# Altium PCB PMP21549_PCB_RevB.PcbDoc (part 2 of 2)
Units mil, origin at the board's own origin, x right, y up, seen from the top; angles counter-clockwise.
Board outline 4798 x 2992 mil, 2 copper layers (Top Layer, Bottom Layer), stack 62 mil thick; 82 components, 39 nets, 178 pads, 21 vias.
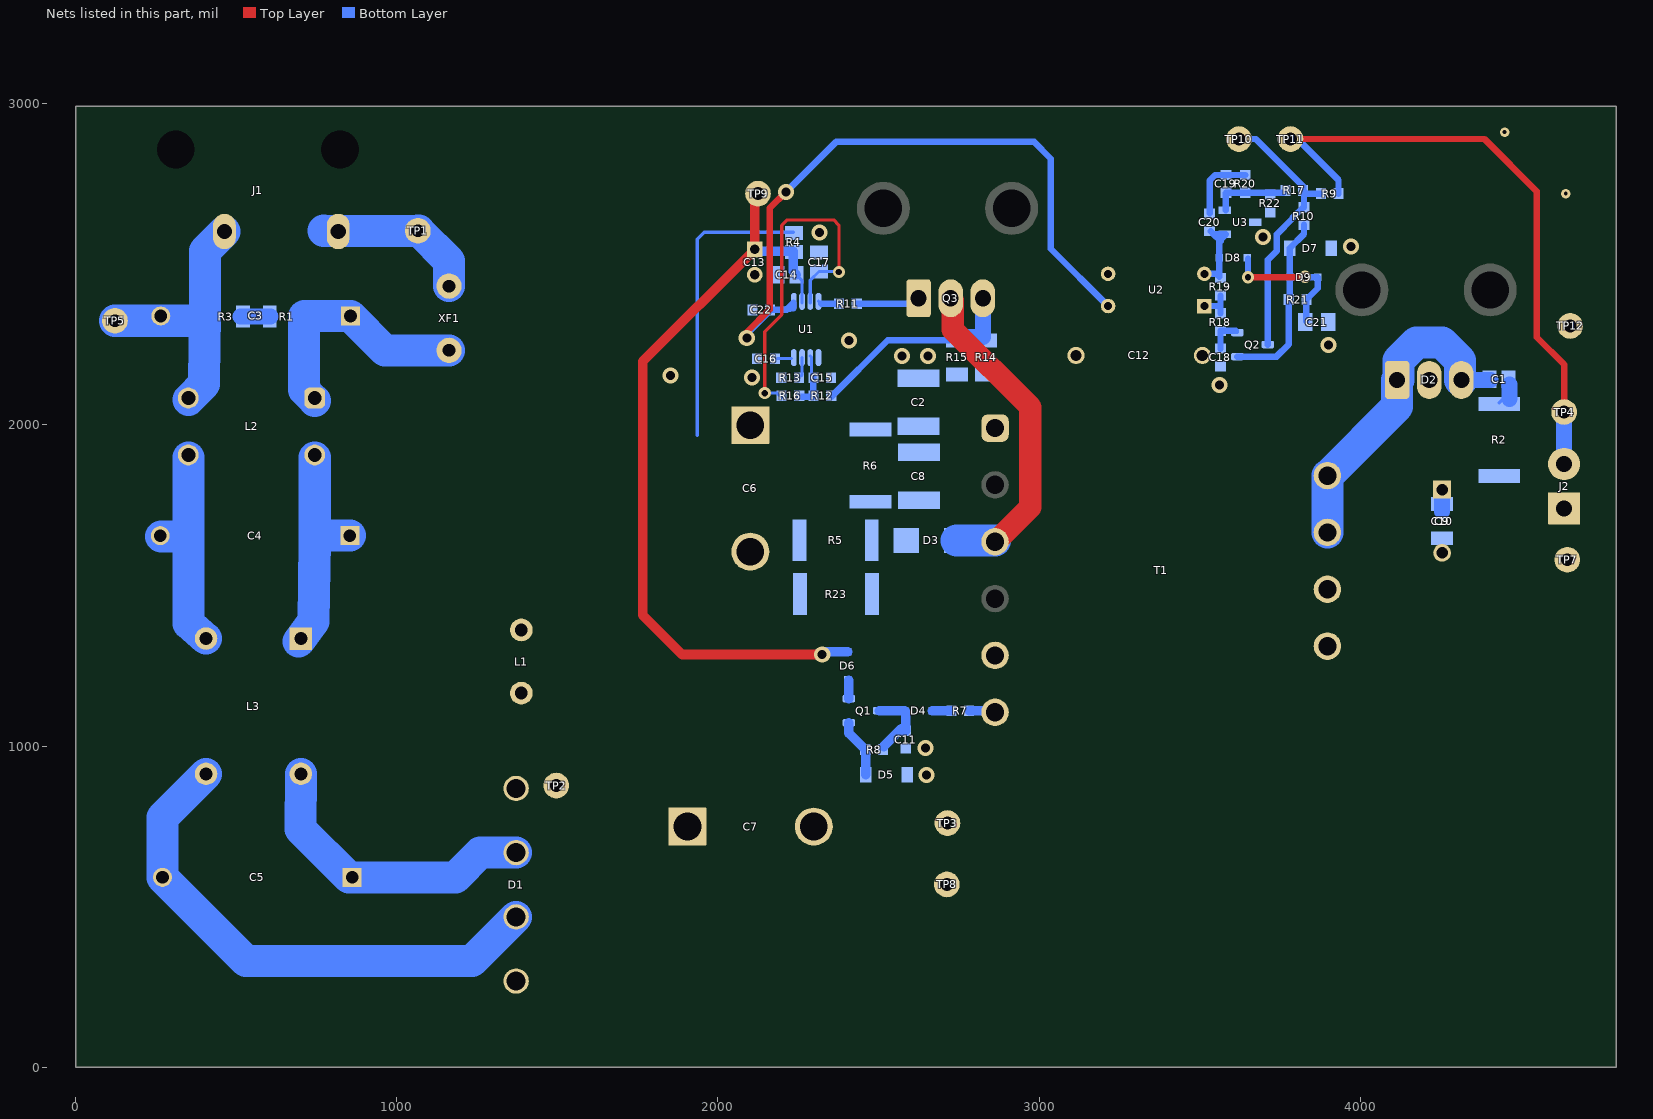
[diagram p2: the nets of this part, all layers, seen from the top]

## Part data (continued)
R18 R19: library part CMP-0022109-4, "RES, 1.00 k, 1%, 0.1 W, 0603", Manufacturer=Vishay-Dale, Power_W=100mW, Supplier Part Number 1=541-1.00KHCT-ND, TempCo="100 ppm/C", Tolerance_%=1%, Value2=0.1W, Value_Code=1k00, ValueDisplayed=1.00k
R20: library part CMP-0022684-3, "RES, 10.0 k, 1%, 0.1 W, 0603", Manufacturer=Panasonic, Power_W=100mW, Supplier Part Number 1=P10.0KHCT-ND, TempCo="100 ppm/C", Tolerance_%=1%, Value2=0.1W, Value_Code=10k0, ValueDisplayed=10.0k
R21: library part CMP-0021990-3, "RES, 100 k, 1%, 0.1 W, 0603", Manufacturer=Vishay-Dale, Power_W=100mW, Supplier Part Number 1=541-100KHCT-ND, TempCo="100 ppm/C", Tolerance_%=1%, Value2=0.1W, Value_Code=100k
R22: library part CMP-0022277-3, "RES, 2.49 k, 1%, 0.1 W, 0603", Manufacturer=Vishay-Dale, Power_W=100mW, Supplier Part Number 1=541-2.49KHCT-ND, TempCo="100 ppm/C", Tolerance_%=1%, Value2=0.1W, Value_Code=2k49, ValueDisplayed=2.49k
T1: library part CMP-0078825-2, "Transformer, 1050 uH, TH", Manufacturer="Renco Electronics", ValueDisplayed=1.05mH
TP1 TP2 TP4 TP5 TP9 TP10 TP11: library part CMP-0055137-1, "Test Point, Miniature, Red, TH", Color=Red, Manufacturer=Keystone, Supplier Part Number 1=36-5000-ND
TP3 TP7 TP8 TP12: library part CMP-0055138-1, "Test Point, Miniature, Black, TH", Color=Black, Manufacturer=Keystone, Supplier Part Number 1=36-5001-ND
U1: library part CMP-0072830-2, "AC-DC Current Mode PWM Controller, DGK0008A (VSSOP-8)", Manufacturer="Texas Instruments"
U2: library part CMP-0006173-3, "Optocoupler, 5 kV, 80-160% CTR, TH", Manufacturer="Fairchild Semiconductor", Supplier Part Number 1=FOD817A-ND, Voltage_Isolation_Vrms=5kV
U3: library part CMP-0033091-1, "Adjustable Precision Shunt Regulator, 34 ppm / degC, 100 mA, -40 to 85 degC, 3-pin SOT-23 (DBZ), Green (RoHS & no Sb/Br)", Manufacturer="Texas Instruments", Rating=Catalog, Temp Coeff(Max)(ppm/ degree C)=92, Temp Coeff(Typ)(ppm/ degree C)=34
XF1: library part CMP-0003627-1, "Fuse Holder, TR5, TH", Manufacturer=Littelfuse, Supplier Part Number 1=WK6235-ND

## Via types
v1: diameter 50, hole 28, Top Layer to Bottom Layer, 15 vias
v2: diameter 38, hole 20, Top Layer to Bottom Layer, 4 vias
v3: diameter 29.92, hole 12.2, Top Layer to Bottom Layer, 2 vias

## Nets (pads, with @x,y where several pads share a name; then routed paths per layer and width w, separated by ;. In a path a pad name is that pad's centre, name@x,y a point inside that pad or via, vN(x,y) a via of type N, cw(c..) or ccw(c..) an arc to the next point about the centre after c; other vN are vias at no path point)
NetC1_1: C1.1 R2.2 | length 84.9
  Bottom Layer w10: R2.2@4432.82,2069.14 4462,2098.32
  Bottom Layer w50: R2.2@4465,2081.32 C1.1@4465,2125
NetC1_2: C1.2 D2.1 D2.3 T1.9 T1.10 | length 1021.9
  Bottom Layer w50: D2.3@4315,2140 C1.2@4406.16,2140
  Bottom Layer w100: T1.9@3898,1665 T1.10@3898,1842 ; T1.10@3901,1843 4115,2057 D2.1@4115,2140 4119.13,2140 4119.13,2200.77 4175.29,2256.93 4254.71,2256.93 4310.87,2200.77 4310.87,2140 D2.3@4315,2140
NetC2_1: C2.1 C6.1 C8.1 L1.2 R4.2 R5.2 R6.2 R23.2 T1.1 | length 918.9
  Bottom Layer w10: 1936,1967 1936,2578 1957.53,2599.53 R4.2@2235,2599.53
NetC3_1: C3.1 L2.1 R1.2 XF1.1 | length 773.1
  Bottom Layer w10: R1.2@711,2337 R1.2@713,2339
  Bottom Layer w100: R1.2@711,2337 711,2109.17 L2.1@745,2075.17 ; R1.2@713,2339 C3.1@856,2339 963,2232 XF1.1@1163,2232
NetC3_2: C3.2 J1.2 L2.4 R3.1 TP5.1 | length 843.4
  Bottom Layer w10: L2.4@351.3,2075.17 L2.4@351.3,2078
  Bottom Layer w100: TP5.1@122.76,2324.25 R3.1@394,2324.25 ; L2.4@351.3,2078 400,2126.7 400,2144.8 403.27,2337.19 403.27,2541.68 J1.2@463.67,2602.08
NetC4_1: C4.1 L2.2 L3.1 | length 710.3
  Bottom Layer w100: L3.1@694,1325 741,1388 745,1633 745,1685 ; L2.2@745,1898 745,1685 ; C4.1@854.28,1655 775,1655 745,1685
NetC4_2: C4.2 L2.3 L3.2 | length 673.2
  Bottom Layer w100: C4.2@266.72,1652 351.3,1652 ; L2.3@351.3,1898 351.3,1652 ; L3.2@406.36,1334.63 351.3,1382 351.3,1652
NetC5_1: C5.1 D1.2 L3.4 | length 937.4
  Bottom Layer w100: L3.4@701.64,913.37 700.97,741.03 851,591 C5.1@861.28,591 1183,591 1260,668 D1.2@1372,668
NetC5_2: C5.2 D1.3 L3.3 | length 1644.3
  Bottom Layer w100: L3.3@406.36,913.37 270.72,777.73 C5.2@270.72,591 530.72,331 1235,331 D1.3@1372,468
NetC7_1: C7.1 D1.1 L1.1 TP2.1
NetC8_2: C8.2 D3.1 R5.1 R6.1 R23.1
NetC9_1: C9.1 C10.1 D2.2 J2.2 R2.1 R9.2 TP4.1 TP11.1 | length 2039.4
  Top Layer w20: TP11.1@3783,2890 4386.87,2890 4550,2726.87 4550,2272.64 4635,2187.64 TP4.1@4635,2040
  Bottom Layer w20: TP11.1@3783,2890 TP11.1@3805,2890 ; TP11.1@3812,2890 TP11.1@3805,2890 ; R9.2@3932.56,2720 3932.56,2762.44 TP11.1@3805,2890
  Bottom Layer w50: 4255,1729.52 C10.1@4255,1753.15 C9.1@4255,1798.42 ; J2.2@4635,1878 TP4.1@4635,2040
NetC11_1: C11.1 D4.1 Q1.3 R8.2 | length 239.9
  Bottom Layer w10: C11.1@2570.12,1045.02 C11.1@2570.12,1047.56
  Bottom Layer w30: Q1.3@2502.24,1110 D4.1@2581.69,1110 2585,1106.69 C11.1@2585,1047.56 C11.1@2570.12,1047.56 ; R8.2@2516,998 C11.1@2572.02,1054.02
NetC13_1: C13.1 C14.1 D6.1 R4.1 TP9.1 U1.2 | length 2440.2
  Top Layer w30: TP9.1@2125,2720 2115,2710 C13.1@2115,2546.38 1766,2197.38 1766,1408 1889,1285 v1(2325,1285)
  Bottom Layer w10: C14.1@2244.53,2467.01 2262.2,2449.33 U1.2@2262.2,2379.68
  Bottom Layer w30: C13.1@2120.91,2540.47 2235,2540.47 2235,2476.54 C14.1@2244.53,2467.01 ; v1(2325,1285) 2333.31,1293.31 D6.1@2405,1293.31
NetC15_1: C15.1 R12.1 R16.2 U1.6 | length 176.2
  Bottom Layer w10: U1.6@2287.8,2214.33 2291.65,2210.47 2291.65,2152.8 C15.1@2297.44,2147.01
  Bottom Layer w20: R16.2@2252.56,2087.01 2297.44,2087.01 C15.1@2297.44,2147.01
NetC16_1: C16.1 U1.8 | length 46.7
  Bottom Layer w10: C16.1@2182.56,2207.01 U1.8@2229.29,2207.01
NetC17_1: C17.1 R16.1 U1.3 | length 1107.6
  Top Layer w10: v2(2146,2099) 2146,2290.44 2198.87,2343.31 2198.87,2620.87 2216,2638 2361,2638 2377,2622 v2(2377,2476)
  Bottom Layer w10: v2(2146,2099) 2185.45,2099 R16.1@2197.44,2087.01 ; U1.3@2287.8,2379.68 2287.8,2450.28 C17.1@2315,2477.48 v2@2375.52,2477.48
NetC18_1: C18.1 Q2.2 R18.2 | length 109.7
  Bottom Layer w10: Q2.2@3612.72,2292.44 Q2.2@3617.76,2287.4
  Bottom Layer w20: C18.1@3565,2237.56 R18.2@3565,2292.44 Q2.2@3612.72,2292.44
NetC19_1: C19.1 R17.1 R20.2 R22.2 U3.2 | length 243.7
  Bottom Layer w10: C19.1@3581.25,2721.8 C19.1@3582.2,2722.76 ; R17.1@3760.2,2722.76 R17.1@3767.44,2730
  Bottom Layer w20: U3.2@3581.25,2667.72 C19.1@3581.25,2721.8 ; C19.1@3582.2,2722.76 R20.2@3642.2,2722.76 R17.1@3760.2,2722.76
NetC19_2: C19.2 C20.1 R20.1 | length 220
  Bottom Layer w20: C20.1@3531,2658.56 3531,2760 3548.87,2777.87 C19.2@3582.2,2777.87 R20.1@3642.2,2777.87
NetC20_2: C20.2 D8.2 R19.1 U2.2 U3.1 | length 272.2
  Bottom Layer w20: U2.2@3515,2470 3552.56,2470 3561.69,2460.87 D8.2@3561.69,2520 3561.69,2572.91 3581.69,2592.91 C20.2@3544.84,2592.91 ; C20.2@3535,2602.76 C20.2@3544.84,2592.91 ; 3566.5,2571.26 3563.27,2574.49 C20.2@3544.84,2592.91
NetC21_1: C21.1 D8.1 D9.2 R21.1 | length 425.5
  Top Layer w20: v2(3650.62,2459.88) v2@3827.62,2459.88
  Bottom Layer w20: v2(3650.62,2459.88) D8.1@3650.62,2517.69 ; v2@3829.5,2460 D9.2@3868.31,2460 3868.31,2425.75 R21.1@3832.56,2390 C21.1@3832.56,2322.91
  other v2: 3828.62,2460.88
NetC22_1: C22.1 U1.1 U2.4 | length 2184.3
  Top Layer w20: v1(2090,2270) 2090,2288 2161,2359 2161,2674 v1(2212,2725)
  Bottom Layer w20: v1(2090,2270) 2090,2282.8 2162.56,2355.36 C22.1@2162.56,2358 ; C22.1@2161,2359 2214.79,2359 2216.23,2360.45 ; 2212.01,2360 2216.23,2360.45 ; v1@2217,2730 2368,2881 2985,2881 3037,2829 3037,2548 U2.4@3215,2370 ; 2216.23,2360.45 2235.47,2379.68 2235.47,2362.47 2216.23,2360.45
NetD3_2: D3.2 Q3.2 T1.3 | length 1023.5
  Top Layer w70: Q3.2@2725,2394.2 2732,2387.2 2732,2296 2973,2055 2973,1744 T1.3@2866,1637
  Bottom Layer w100: D3.2@2743.74,1640 T1.3@2863,1640
NetD4_2: D4.2 R7.2 | length 59.1
  Bottom Layer w30: D4.2@2668.31,1110 R7.2@2727.44,1110
NetD5_1: D5.1 Q1.1 R8.1 | length 180.1
  Bottom Layer w30: Q1.1@2407.76,1072.6 2407.76,1039.69 R8.1@2457.44,990 ; D5.1@2460.53,910 R8.1@2460.53,986.91
NetD6_2: D6.2 Q1.2 | length 56.5
  Bottom Layer w30: Q1.2@2407.76,1147.4 D6.2@2407.76,1203.94
NetD7_1: D7.1 D9.1 Q2.1 R10.1 R21.2 | length 567.1
  Bottom Layer w20: Q2.1@3617.76,2212.6 3739.6,2212.6 3777.44,2250.44 R21.2@3777.44,2390 3780.53,2393.09 D7.1@3780.53,2550 3825,2594.47 R10.1@3825,2622.44
NetJ1_1: J1.1 TP1.1 XF1.2 | length 507.3
  Bottom Layer w10: 1002.68,2604.33 1002.76,2604.25
  Bottom Layer w100: 772.76,2604.33 818.02,2603.97 TP1.1@1066,2604.25 1068.56,2604.25 1163,2509.82 XF1.2@1163,2432
NetQ2_3: Q2.3 R9.1 R10.2 R17.2 TP10.1 | length 854.9
  Bottom Layer w20: TP10.1@3622.6,2890 3675,2890 3822.56,2742.44 R17.2@3822.56,2730 ; Q2.3@3712.24,2250 3712.24,2513.5 3740.87,2542.13 3740.87,2593.43 3790.39,2642.95 3790.39,2645.59 3822.36,2677.56 R10.2@3825,2677.56 3825,2727.56 3832.56,2720 R9.1@3877.44,2720
NetQ3_1: Q3.1 R11.2 | length 199.6
  Bottom Layer w20: R11.2@2432.56,2377.01 2607.8,2377.01 Q3.1@2625,2394.2
NetQ3_3: Q3.3 R12.2 R14.2 R15.2 | length 656.5
  Bottom Layer w20: R12.2@2352.56,2087.01 2528.7,2263.15 R15.2@2745,2263.15
  Bottom Layer w50: R15.2@2755,2273.15 2825,2273.15 Q3.3@2825,2394.2
NetR1_1: R1.1 R3.2 | length 93.7
  Bottom Layer w50: R3.2@513.57,2337 R1.1@607.28,2337
NetR7_1: R7.1 T1.6 | length 82.5
  Bottom Layer w10: T1.6@2858,1110 T1.6@2863,1105
  Bottom Layer w30: R7.1@2782.56,1110 T1.6@2858,1110
NetR11_1: R11.1 U1.4 | length 67.3
  Bottom Layer w10: U1.4@2313.39,2384.61 U1.4@2321.29,2376.7
  Bottom Layer w20: U1.4@2321.29,2376.7 R11.1@2377.44,2376.7
NetR13_2: R13.2 U1.7 | length 66.4
  Bottom Layer w10: R13.2@2252.56,2147.01 2262.2,2156.65 U1.7@2262.2,2209.41
NetR18_1: R18.1 R19.2 U2.1 | length 104.9
  Bottom Layer w20: U2.1@3515,2370 3565,2370 ; R18.1@3565,2347.56 3565,2370 ; R19.2@3565,2402.44 3565,2370
"pwr gnd": C2.2 C6.2 C7.2 C11.2 C12.2 C13.2 C14.2 C15.2 C16.2 C17.2 C22.2 D1.4 D5.2 R13.1 R14.1 R15.1 T1.5 TP3.1 TP8.1 U1.5 U2.3
  other v1: 2649,910 2646,994 2106,2148 1853,2153 2574,2215 2655,2215 2408,2263 2317,2599
"SEC GND": C9.2 C10.2 C12.1 C18.2 C21.2 D7.2 J2.1 R22.1 T1.7 T1.8 TP7.1 TP12.1 U3.3
  other v1: 3562,2124 3901,2249 3971,2555 3698,2585
  other v3: 4640,2720 4450,2911.4
pads on no net: H1.MH1 H1.MH2 H2.MH1 H2.MH2 J1.MH1 J1.MH2 T1.2 T1.4

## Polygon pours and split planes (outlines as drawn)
NetC8_2 on Bottom Layer "BOTTOM_LAYER_NETC8_2_P003" (solid, remove dead copper, pour order 3): 2709,1826 2709,1392 2401.19,1392 2401.19,1826
"SEC GND" on Bottom Layer "BOTTOM_LAYER_SEC_GND_P022" (solid, remove dead copper, pour order 22): 3471,2940 3471,2071 3832,2071 3832,50 4747.53,50 4752.57,2940
NetC9_1 on Bottom Layer "BOTTOM_LAYER_NETC9_1_P020" (solid, remove dead copper, pour order 20): 4167,2205 4278,2205 4287,2196 4287,1967 4301,1953 4709,1953 4709,1811 4701,1803 4314,1803 4281,1770 4192,1770 4173,1789
"pwr gnd" on Bottom Layer "BOTTOM_LAYER_PWR_GND_P016" (solid, remove dead copper, pour order 16): 1285.23,50 2955,50 2955,2080 3019,2144 3241.76,2144 3241.76,2940 1482,2940 1482,436 1382,336 1287,336
NetC2_1 on Bottom Layer "BOTTOM_LAYER_NETC2_1_P001" (solid, remove dead copper, pour order 1): 1294,1313 2403.3,1313 2403.3,1840 2932.63,1840 2932.63,2060 1294,2060
NetC9_1 on Top Layer "TOP_LAYER_NETC9_1_P000" (solid, remove dead copper, pour order 0): 4284.3,1743.3 4343,1802 4701,1802 4701,1947 4695,1953 4170.63,1953 4170.63,1791.37 4218.7,1743.3
"SEC GND" on Top Layer "TOP_LAYER_SEC_GND_P018" (solid, remove dead copper, pour order 18): 3469,2940 3469,2085 3832,2085 3832,50 4750,50 4750,2940
"pwr gnd" on Top Layer "TOP_LAYER_PWR_GND_P005" (solid, remove dead copper, pour order 5): 1287,50 2955,50 2955,2051 3019,2144 3241.76,2144 3241.76,2940 1482,2940 1477,429 1287,245.11
NetC7_1 on Top Layer "TOP_LAYER_NETC7_1_P004" (solid, remove dead copper, pour order 4): 1979,674 1538,674 1401,811 1291,811 1291,1202 1298,1209 1301,1206 1586,1206 1979,822.05

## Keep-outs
Keep-Out Layer:
  text ".Layer_Name" at 577,-858.49 h60

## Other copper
Top Layer:
  text ".Layer_Name" at 577,-858.49 h60
Bottom Layer:
  text ".Layer_Name" at 577,-858.49 h60

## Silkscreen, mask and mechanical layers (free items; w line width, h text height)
Top Overlay:
  region: 1000,213 700,213 700,113 1000,113
  text "'.PRJ_Number'.PCB_Rev-" at 117,130.77 h108.27
  text ".Layer_Name" at 577,-858.49 h60
Bottom Overlay:
  lines w10: 3643,2810 3667,2834 3669,2834
  text ".Layer_Name" at 577,-858.49 h60
Top Paste:
  text ".Layer_Name" at 577,-858.49 h60
Bottom Paste:
  text ".Layer_Name" at 577,-858.49 h60
Top Solder:
  text ".Layer_Name" at 577,-858.49 h60
  text ".Layer_Name" at 577,-858.49 h60
Bottom Solder:
  text ".Layer_Name" at 577,-858.49 h60
Drill Guide:
  text ".Layer_Name" at 577,-858.49 h60
M1 Board Outline:
  lines w10: 0,2992 0,0 4798,0 4799,2992 1,2992
  text ".Layer_Name" at 577,-858.49 h60
M2 Board Dimensions:
  rectangle: 125,-400 500,-275
  rectangle: 0,-275 125,-150
  lines w7: 0,-275 1000,-275 ; 125,-400 125,-150 ; 250,-400 250,-150 ; 500,-400 500,-150 ; 750,-400 750,-150 ; 0,-400 0,-150 1000,-150 1000,-400 0,-400
  text ".Layer_Name" at 577,-858.49 h60
M3 3D STEP Top:
  text ".Layer_Name" at 577,-858.49 h60
M4 3D STEP Bottom:
  text ".Layer_Name" at 577,-858.49 h60
M5 Assembly Top:
  lines w10: -292,-930.17 6308,-930.17 ; -292,-726.83 6310,-726.83 ; -292,-523.5 -292,-1133.5 3713,-1133.5 6310,-1133.5 6310,-523.5 -291.5,-523.5 -291.5,-1133.5 1284,-1133.5 ; 2173,-1133.5 2173,-523.5 ; 3440,-726.83 3440,-523.5 ; 4280,-726.83 4280,-523.5 ; 4902,-1140 4902,-937.17
  text "COMPONENTS MARKED 'DNP' SHOULD NOT BE POPULATED." at 1153.5,-318.5 h60
  text "ASSEMBLY VARIANT:" at 1153,-434 h60
  text ".VariantName" at 2189,-434 h60
  text "PCB VIEWED FROM TOP SIDE" at -228.5,-655.67 h60
  text "BOARD #:" at 2248,-655.67 h60
  text ".PRJ_Number" at 2793.5,-655.67 h60
  text "REV:" at 3638,-655.67 h60
  text ".PCB_Rev" at 3929.5,-655.67 h60
  text "SVN REV:" at 4476,-655.67 h60
  text ".VersionControl_RevNumber" at 4982,-655.67 h60
  text "TID #:" at 2248,-859 h60
  text ".TID" at 2793.5,-859 h60
  text "PLOT NAME =" at -228.5,-1064.34 h60
  text ".plot_File_Name" at 577,-1064.34 h60
  text "GENERATED    :" at 2250,-1064.34 h60
  text ".Print_Date" at 3119.5,-1064.34 h60
  text ".Print_Time" at 3848.5,-1064.34 h60
  text "TEXAS INSTRUMENTS" at 5113,-1064.34 h60
M6 Assembly Bottom:
  lines w10: -292.5,-727.33 6309.5,-727.33 ; -290.5,-930.67 6309.5,-930.67 ; 1115.5,-1140.5 1115.5,-937.67 ; 1737.5,-727.33 1737.5,-524 ; 2577.5,-727.33 2577.5,-524 ; 3844.5,-1134 3844.5,-524 ; 4733.5,-1134 6309,-1134 6309,-524 -292.5,-524 -292.5,-1134 2304.5,-1134 6309.5,-1134 6309.5,-524
  text "COMPONENTS MARKED 'DNP' SHOULD NOT BE POPULATED." at 6102,-318 h60
  text ".VariantName" at 5058,-434 h60
  text "ASSEMBLY VARIANT:" at 6097,-434 h60
  text ".VersionControl_RevNumber" at 1035.5,-656.17 h60
  text "SVN REV:" at 1541.5,-656.17 h60
  text ".PCB_Rev" at 2088,-656.17 h60
  text "REV:" at 2379.5,-656.17 h60
  text ".PRJ_Number" at 3224,-656.17 h60
  text "BOARD #:" at 3769.5,-656.17 h60
  text "PCB VIEWED FROM BOTTOM SIDE" at 6246,-656.17 h60
  text ".TID" at 3224,-859.5 h60
  text "TID #:" at 3769.5,-859.5 h60
  text "TEXAS INSTRUMENTS" at 904.5,-1064.84 h60
  text ".Print_Time" at 2169,-1064.84 h60
  text ".Print_Date" at 2898,-1064.84 h60
  text "GENERATED    :" at 3767.5,-1064.84 h60
  text ".plot_File_Name" at 5440.5,-1064.84 h60
  text "PLOT NAME =" at 6246,-1064.84 h60
M9 Title Sheet:
  drawing of 57 lines, arcs and shapes, not listed
  text "1" at 739.84,8036.5 h70
  text "2" at 3235.5,8036.5 h70
  text "3" at 5724.84,8036.5 h70
  text "4" at 8231.51,8036.5 h70
  text "5" at 10730.5,8036.5 h70
  text "6" at 13235.5,8036.5 h70
  text "A" at -416.5,6893.5 h70
  text "A" at 14383.5,6893.5 h70
  text "B" at -416.5,4513.5 h70
  text "B" at 14383.5,4513.5 h70
  text "C" at -416.5,2138.5 h70
  text "C" at 14383.5,2138.5 h70
  text "PROJECT TITLE:" at 11343.5,277.5 h45
  text ".PRJ_Title" at 11393.5,144.17 h70
  text "DESIGNED FOR:" at 11343.5,-23.5 h45
  text ".PRJ_Customer" at 11393.5,-163.5 h70
  text "D" at -416.5,-231.5 h70
  text "D" at 14383.5,-231.5 h70
  text "FILE NAME:" at 11343.5,-323.5 h45
  text ".PCB_File_Name_No_Path" at 11393.5,-443.5 h70
  text "Texas Instruments (TI) and/or its licensors do not warrant the accuracy or completeness of this specification" at 6374,-605.34 h45
  text "ENGINEER:" at 11343.5,-613.5 h45
  text "LAYOUT BY:" at 12848.5,-613.5 h45
  text "or any information contained therein. TI and/or its licensors do not warrant that this design will meet" at 6329.01,-718 h45
  text ".PRJ_Engineer" at 11393.5,-768.49 h70
  text ".PCB_Layout" at 12899,-768.49 h70
  text "the specifications, will be suitable for your application or fit for any particular purpose, or will operate in" at 6329.01,-830.67 h45
  text ".Layer_Name" at 577,-858.49 h60
  text "ALTIUM DESIGNER VERSION:" at 12848.5,-923.5 h45
  text "an implementation. TI and/or its licensors do not warrant that the design is production worthy. You should" at 6329.01,-943.33 h45
  text "completely validate and test your design implementation to confirm the system functionality for your application." at 6374,-1056 h45
  text ".print_Scale" at 11393.5,-1056.83 h70
  text ".Application_BuildNumber" at 12899,-1056.83 h70
  text "1" at 739.84,-1263.5 h70
  text "2" at 3235.5,-1263.5 h70
  text "3" at 5724.84,-1263.5 h70
  text "4" at 8231.51,-1263.5 h70
  text "5" at 10730.5,-1263.5 h70
  text "6" at 13235.5,-1263.5 h70
M10 Fab Notes:
  drawing of 189 lines, arcs and shapes, not listed
  text "DESIGN INFORMATION" at 12382.02,6356.17 h60
  text "MIN. TRACK WIDTH:" at 11737.46,6224.05 h60
  text "8" at 12833.7,6224.05 h60
  text "MIL" at 12988.46,6224.05 h60
  text "MIN. CLEARANCE:" at 11737.46,6099.92 h60
  text "0.2" at 12773.7,6099.93 h60
  text "mm" at 12988.46,6099.92 h60
  text "MIN. VIA PAD SIZE:" at 11737.46,5975.8 h60
  text "24" at 12803.71,5975.8 h60
  text "MIL" at 12988.46,5975.8 h60
  text "0.05mm (2MIL)" at 12432.46,5845.9 h60
  text "MINIMUM ANNULAR RING" at 11408.23,5837.67 h60
  text "EXTERNAL" at 13140.46,5837.67 h60
  text "PER" at 11608.23,5727.55 h60
  text "IPC-D-275 CLASS 2 LEVEL C" at 11828.23,5727.54 h60
  text "MIL, HOLES" at 13316.46,5627.07 h60
  text "+/-" at 12924,5618.48 h60
  text "+/-" at 13778,5618.48 h60
  text "REGISTRATION TOLERANCES:" at 11408.23,5617.42 h60
  text "METAL" at 12608,5617.42 h60
  text "5" at 13184.2,5617.42 h60
  text "3" at 14017.2,5617.42 h60
  text "MIL" at 14133.46,5617.42 h60
  text "HOLE SIZE TOLERANCE (UNLESS OTHERWISE SPECIFIED):" at 11408.23,5519.1 h60
  text "+/-" at 13778,5516.23 h60
  text "3" at 14017.2,5515.17 h60
  text "MIL" at 14133.46,5515.17 h60
  text "MATERIAL:" at 11333.46,5377.52 h60
  text "FR-4 High Tg" at 12319.9,5249 h60
  text "X" at 12175.46,5241.01 h60
  text "FR-408" at 11754.46,5236.49 h60
  text "OTHER" at 13242.46,5236.49 h60
  text "62 MIL (1.6mm) +/-10%" at 12074.56,5093.46 h60
  text "X" at 11954.46,5091.01 h60
  text "THICKNESS:" at 11408.23,5085.24 h60
  text "OTHER" at 13359.46,5085.24 h60
  text "TOLERANCE:" at 11408.23,4946.92 h60
  text "X" at 12256.46,4946.92 h60
  text "ANSI IPC-6012 TYPE 3 CLASS 2" at 12434.48,4946.92 h60
  text "OTHER +/-" at 12434.46,4802.73 h60
  text "BOW & TWIST:" at 11408.23,4657.54 h60
  text "X" at 12256.46,4657.54 h60
  text "ANSI IPC-6012 TYPE 3 CLASS 2" at 12434.48,4657.54 h60
  text "OTHER +/-" at 12434.46,4510.85 h60
  text "DRILLING:" at 11333.46,4380.23 h60
  text "NC_DRILL FILES" at 13094.46,4275.04 h60
  text "REFERENCE:" at 11408.23,4271.1 h60
  text "X" at 12065.46,4271.01 h60
  text "AS SHOWN" at 12243.46,4271.1 h60
  text "X" at 12966.46,4271.1 h60
  text "OTHER" at 13392.46,4128.85 h60
  text "PTH COPPER THICKNESS:" at 11407.91,4125.32 h60
  text "X" at 12547.14,4125.32 h60
  text "20-30 um" at 12675.14,4125.32 h60
  text "BOARD FINISH:" at 11333.46,3977.73 h60
  text "SILKSCREEN:" at 11488.68,3867.6 h60
  text "X" at 12446.46,3867.6 h60
  text "TOP" at 12563.46,3867.6 h60
  text "X" at 12956.46,3867.6 h60
  text "BOTTOM" at 13074.46,3867.6 h60
  text "SILKSCREEN COLOR:" at 11488.68,3712.41 h60
  text "X" at 12445.46,3712.41 h60
  text "WHITE" at 12563.46,3712.41 h60
  text "OTHER" at 13074.46,3712.41 h60
  text "X" at 12576.46,3568.96 h60
  text "GREEN" at 12694.46,3568.96 h60
  text "OTHER" at 13312.46,3568.96 h60
  text "SOLDER RESIST COLOR:" at 11488.68,3562.1 h60
  text "X" at 12576.46,3414.71 h60
  text "MATTE" at 12694.46,3414.71 h60
  text "SEMI-GLOSS" at 13312,3414.07 h60
  text "IMMERSION GOLD (ENIG)" at 12394.46,3241.94 h60
  text "ENEPIG" at 13732,3234.72 h60
  text "SURFACE FINISH:" at 11333.46,3233.72 h60
  text "X" at 12216.46,3233.72 h60
  text "IMM. TIN/SILVER OR EQUIV" at 11663,3096.4 h60
  text "OTHER" at 13094.46,3092.47 h60
  text "ARRAY/PANEL:" at 11333.46,2937.09 h60
  text "CUT AND TRIM PER M1 BOARD OUTLINE" at 12394.46,2928.87 h60
  text "N.C. ROUTE" at 12394.46,2792.9 h60
  text "X" at 13082.46,2792.9 h60
  text "V. SCORE" at 13260.46,2792.9 h60
  text "CERTIFICATION:" at 11333.46,2663.77 h60
  text "MATERIALS AND WORKMANSHIP FOR ALL PCBS" at 12058.46,2663.77 h60
  text "TO MEET OR EXCEED THE REQUIREMENTS OF:" at 12058.46,2569.71 h60
  text "X" at 11695.97,2441.08 h60
  text "ANSI IPC-A-600F CLASS ->" at 11823.96,2441.08 h60
  text "X" at 13471.97,2441.08 h60
  text "2" at 13581.96,2441.08 h60
  text "1" at 13266.96,2439.58 h60
  text "3" at 13935.96,2439.58 h60
  text "X" at 12507.97,2293.39 h60
  text "RoHS" at 12635.96,2293.39 h60
  text "OTHER" at 13280.36,2293.39 h60
  text "PER ORDER" at 13677.42,2293.39 h60
  text "ALL BOARDS MUST MEET OR EXCEED UL94-V0 REQUIREMENTS." at 11361,2139.57 h60
  text "PCB MUST BEAR THE UL94V-0 UL REGISTERED MATERIAL ID NUMBER" at 11361,2023.5 h60
  text "ADDITIONAL REQUIREMENTS:" at 11333.46,1854.08 h60
  text "MICROSECTION:" at 11408.23,1746.95 h60
  text "YES" at 12313.96,1746.95 h60
  text "REQUIRED" at 13175.46,1602.62 h60
  text "BARE BOARD ELEC. TEST:" at 11408.23,1599.76 h60
  text "NONE" at 12713.96,1599.76 h60
  text "X" at 13057.46,1599.76 h60
  text "PER ORDER" at 13767.46,1599.76 h60
  text "XX MIL VIAS REQUIRE NON-CONDUCTIVE FILL AND PLANARIZE" at 11576.38,1394.82 h59
  text "XX MIL VIAS REQUIRE CONDUCTIVE FILL AND PLANARIZE" at 11584.38,1290.84 h60
  text "OUTER XX MIL TRACES REQUIRE 50 OHM SINGLE-ENDED IMPEDANCE" at 11583.39,1127.46 h58
  text "LAYER 2 & 3 (INNER LAYERS) XX MIL WIDE, XX MIL SPACE / TRACES REQUIRE 100 OHM DIFFERENTIAL IMPEDANCE" at 11575.39,891.74 h60
  text ".Layer_Name" at 577,-858.49 h60
M11 Gerber Information:
  lines w10: -292,-930.17 6308,-930.17 ; -292,-726.83 6310,-726.83 ; -292,-523.5 -292,-1133.5 3713,-1133.5 6310,-1133.5 6310,-523.5 -291.5,-523.5 -291.5,-1133.5 1284,-1133.5 ; 2173,-1133.5 2173,-523.5 ; 3440,-726.83 3440,-523.5 ; 4280,-726.83 4280,-523.5 ; 4902,-1140 4902,-937.17
  text "ALL ARTWORK VIEWED FROM TOP SIDE" at -228.5,-655.67 h60
  text "BOARD #:" at 2248,-655.67 h60
  text ".PRJ_Number" at 2793.5,-655.67 h60
  text "REV:" at 3638,-655.67 h60
  text ".PCB_Rev" at 3929.5,-655.67 h60
  text "SVN REV:" at 4476,-655.67 h60
  text ".VersionControl_RevNumber" at 4982,-655.67 h60
  text "LAYER NAME =" at -228.5,-858.49 h60
  text "TID #:" at 2248,-859 h60
  text ".TID" at 2793.5,-859 h60
  text "PLOT NAME =" at -228.5,-1064.34 h60
  text ".plot_File_Name" at 577,-1064.34 h60
  text "GENERATED    :" at 2250,-1064.34 h60
  text ".Print_Date" at 3119.5,-1064.34 h60
  text ".Print_Time" at 3848.5,-1064.34 h60
  text "TEXAS INSTRUMENTS" at 5113,-1064.34 h60
M12 Stackup:
  drawing of 191 lines, arcs and shapes, not listed
  text "Layer" at 9797.84,7582.5 h60
  text "Name" at 10207.76,7582.5 h60
  text "Material" at 11137.5,7582.5 h60
  text "Thickness" at 11997.27,7582.5 h60
  text "Constant" at 12647.1,7582.5 h60
  text "Board Layer Stack" at 13216.96,7582.5 h60
  text "1" at 9797.84,7462.5 h60
  text "Top Overlay" at 10207.76,7462.5 h60
  text "2" at 9797.84,7342.5 h60
  text "Top Solder" at 10207.76,7342.5 h60
  text "Solder Resist" at 11137.5,7342.5 h60
  text "0.40mil" at 11997.27,7342.5 h60
  text "3.5" at 12647.1,7342.5 h60
  text "3" at 9797.84,7222.5 h60
  text "Top Layer" at 10207.76,7222.5 h60
  text "Copper" at 11137.5,7222.5 h60
  text "1.40mil" at 11997.27,7222.5 h60
  text "4" at 9797.84,7102.5 h60
  text "Dielectric1" at 10207.76,7102.5 h60
  text "FR-4" at 11137.5,7102.5 h60
  text "59.20mil" at 11997.27,7102.5 h60
  text "4.8" at 12647.1,7102.5 h60
  text "5" at 9797.84,6982.5 h60
  text "Bottom Layer" at 10207.76,6982.5 h60
  text "Copper" at 11137.5,6982.5 h60
  text "1.40mil" at 11997.27,6982.5 h60
  text "6" at 9797.84,6862.5 h60
  text "Bottom Solder" at 10207.76,6862.5 h60
  text "Solder Resist" at 11137.5,6862.5 h60
  text "0.40mil" at 11997.27,6862.5 h60
  text "3.5" at 12647.1,6862.5 h60
  text "7" at 9797.84,6742.5 h60
  text "Bottom Overlay" at 10207.76,6742.5 h60
  text ".Layer_Name" at 577,-858.49 h60
M13 Component Bodies Top:
  text ".Layer_Name" at 577,-858.49 h60
M14 Component Bodies Bottom:
  text ".Layer_Name" at 577,-858.49 h60
M15 Courtyards Top:
  text ".Layer_Name" at 577,-858.49 h60
M16 Courtyards Bottom:
  text ".Layer_Name" at 577,-858.49 h60
Drill Drawing:
  circle w10: c5363.72,3407.23 r27.63
  lines w10: 5336.09,1639.12 5363.72,1652.93 5391.34,1639.12 5377.53,1666.75 5391.34,1694.37 5363.72,1680.56 5336.09,1694.37 5349.9,1666.75 5336.09,1639.12 ; 5336.09,1777.25 5349.9,1777.25 5349.9,1763.44 5377.53,1763.44 5377.53,1777.25 5391.34,1777.25 5391.34,1804.88 5377.53,1804.88 5377.53,1818.69 5349.9,1818.69 5349.9,1804.88 5336.09,1804.88 5336.09,1777.25 ; 5336.09,1887.76 5336.09,1901.57 5349.9,1915.39 5336.09,1929.2 5336.09,1943.01 5349.9,1943.01 5363.72,1929.2 5377.53,1943.01 5391.34,1943.01 5391.34,1929.2 5377.53,1915.39 5391.34,1901.57 5391.34,1887.76 5377.53,1887.76 5363.72,1901.57 5349.9,1887.76 5336.09,1887.76 ; 5336.09,2012.08 5363.72,2025.89 5391.34,2012.08 5377.53,2039.71 5391.34,2067.33 5363.72,2053.52 5336.09,2067.33 5349.9,2039.71 5336.09,2012.08 ; 5336.09,2164.03 5363.72,2136.4 5391.34,2164.03 5363.72,2191.65 5336.09,2164.03 ; 5336.09,2274.53 5349.9,2274.53 5363.72,2260.72 5377.53,2274.53 5391.34,2274.53 5377.53,2288.35 5391.34,2302.16 5377.53,2302.16 5363.72,2315.97 5349.9,2302.16 5336.09,2302.16 5349.9,2288.35 5336.09,2274.53 ; 5336.09,2564.61 5391.34,2564.61 5363.72,2509.36 5336.09,2564.61 ; 5336.09,2633.68 5391.34,2633.68 5391.34,2688.93 5336.09,2688.93 5336.09,2633.68 ; 5336.09,2758 5391.34,2758 5391.34,2813.25 5336.09,2813.25 5336.09,2758 ; 5336.09,2937.57 5391.34,2937.57 5363.72,2882.32 5336.09,2937.57 ; 5336.09,3020.45 5349.9,3020.45 5349.9,3006.64 5377.53,3006.64 5377.53,3020.45 5391.34,3020.45 5391.34,3048.08 5377.53,3048.08 5377.53,3061.89 5349.9,3061.89 5349.9,3048.08 5336.09,3048.08 5336.09,3020.45 ; 5336.09,3144.77 5349.9,3144.77 5363.72,3130.96 5377.53,3144.77 5391.34,3144.77 5377.53,3158.59 5391.34,3172.4 5377.53,3172.4 5363.72,3186.21 5349.9,3172.4 5336.09,3172.4 5349.9,3158.59 5336.09,3144.77 ; 5347.14,1650.17 5363.72,1658.46 5380.29,1650.17 5372.01,1666.75 5380.29,1683.32 5363.72,1675.04 5347.14,1683.32 5355.43,1666.75 5347.14,1650.17 ; 5347.14,1782.78 5355.43,1782.78 5355.43,1774.49 5372.01,1774.49 5372.01,1782.78 5380.29,1782.78 5380.29,1799.36 5372.01,1799.36 5372.01,1807.64 5355.43,1807.64 5355.43,1799.36 5347.14,1799.36 5347.14,1782.78 ; 5347.14,2769.05 5380.29,2769.05 5380.29,2802.2 5347.14,2802.2 5347.14,2769.05 ; 5347.14,2926.52 5380.29,2926.52 5363.72,2893.37 5347.14,2926.52 ; 5347.14,3150.3 5355.43,3150.3 5363.72,3142.01 5372.01,3150.3 5380.29,3150.3 5372.01,3158.59 5380.29,3166.88 5372.01,3166.88 5363.72,3175.16 5355.43,3166.88 5347.14,3166.88 5355.43,3158.59 5347.14,3150.3
  lines w12: 5286,1601.82 8517.49,1601.82 ; 5286,3466.62 8517.49,3466.62 ; 5623.86,1477.51 5623.86,3590.94 ; 5955.86,1477.51 5955.86,3590.94 ; 6592.43,1477.51 6592.43,3590.94 ; 6851.57,1477.51 6851.57,3590.94 ; 7226.72,1477.51 7226.72,3590.94 ; 7951.05,1477.51 7951.05,3590.94 ; 5286,1477.51 8517.49,1477.51 8517.49,3590.94 5286,3590.94 5286,1477.51
  text "Symbol" at 5360.59,3503.92 h72
  text "Quantity" at 5661.16,3503.92 h72
  text "Finished Hole Size" at 5993.16,3503.92 h72
  text "Plated" at 6629.72,3503.92 h72
  text "Hole Type" at 6888.86,3503.92 h72
  text "Drill Layer Pair" at 7264.02,3503.92 h72
  text "Hole Tolerance" at 7988.35,3503.92 h72
  text "2" at 5661.16,3379.6 h60
  text "118.11mil (3.000mm)" at 5993.16,3379.6 h60
  text "NPTH" at 6629.72,3379.6 h60
  text "Round" at 6888.86,3379.6 h60
  text "Top Layer - Bottom Layer" at 7264.02,3379.6 h60
  text "4" at 5661.16,3255.28 h60
  text "20.00mil (0.508mm)" at 5993.16,3255.28 h60
  text "PTH" at 6629.72,3255.28 h60
  text "Round" at 6888.86,3255.28 h60
  text "Top Layer - Bottom Layer" at 7264.02,3255.28 h60
  text "A" at 5335.31,3245.29 h55.25
  text "4" at 5661.16,3130.96 h60
  text "25.59mil (0.650mm)" at 5993.16,3130.96 h60
  text "PTH" at 6629.72,3130.96 h60
  text "Round" at 6888.86,3130.96 h60
  text "Top Layer - Bottom Layer" at 7264.02,3130.96 h60
  text "15" at 5661.16,3006.64 h60
  text "28.00mil (0.711mm)" at 5993.16,3006.64 h60
  text "PTH" at 6629.72,3006.64 h60
  text "Round" at 6888.86,3006.64 h60
  text "Top Layer - Bottom Layer" at 7264.02,3006.64 h60
  text "2" at 5661.16,2882.32 h60
  text "29.53mil (0.750mm)" at 5993.16,2882.32 h60
  text "PTH" at 6629.72,2882.32 h60
  text "Round" at 6888.86,2882.32 h60
  text "Top Layer - Bottom Layer" at 7264.02,2882.32 h60
  text "4" at 5661.16,2758 h60
  text "35.43mil (0.900mm)" at 5993.16,2758 h60
  text "PTH" at 6629.72,2758 h60
  text "Round" at 6888.86,2758 h60
  text "Top Layer - Bottom Layer" at 7264.02,2758 h60
  text "8" at 5661.16,2633.68 h60
  text "39.37mil (1.000mm)" at 5993.16,2633.68 h60
  text "PTH" at 6629.72,2633.68 h60
  text "Round" at 6888.86,2633.68 h60
  text "Top Layer - Bottom Layer" at 7264.02,2633.68 h60
  text "17" at 5661.16,2509.36 h60
  text "40.00mil (1.016mm)" at 5993.16,2509.36 h60
  text "PTH" at 6629.72,2509.36 h60
  text "Round" at 6888.86,2509.36 h60
  text "Top Layer - Bottom Layer" at 7264.02,2509.36 h60
  text "4" at 5661.16,2385.04 h60
  text "43.31mil (1.100mm)" at 5993.16,2385.04 h60
  text "PTH" at 6629.72,2385.04 h60
  text "Round" at 6888.86,2385.04 h60
  text "Top Layer - Bottom Layer" at 7264.02,2385.04 h60
  text "B" at 5335.31,2375.05 h55.25
  text "8" at 5661.16,2260.72 h60
  text "50.00mil (1.270mm)" at 5993.16,2260.72 h60
  text "PTH" at 6629.72,2260.72 h60
  text "Round" at 6888.86,2260.72 h60
  text "Top Layer - Bottom Layer" at 7264.02,2260.72 h60
  text "10" at 5661.16,2136.4 h60
  text "57.09mil (1.450mm)" at 5993.16,2136.4 h60
  text "PTH" at 6629.72,2136.4 h60
  text "Round" at 6888.86,2136.4 h60
  text "Top Layer - Bottom Layer" at 7264.02,2136.4 h60
  text "4" at 5661.16,2012.08 h60
  text "59.06mil (1.500mm)" at 5993.16,2012.08 h60
  text "PTH" at 6629.72,2012.08 h60
  text "Round" at 6888.86,2012.08 h60
  text "Top Layer - Bottom Layer" at 7264.02,2012.08 h60
  text "4" at 5661.16,1887.76 h60
  text "86.61mil (2.200mm)" at 5993.16,1887.76 h60
  text "PTH" at 6629.72,1887.76 h60
  text "Round" at 6888.86,1887.76 h60
  text "Top Layer - Bottom Layer" at 7264.02,1887.76 h60
  text "4" at 5661.16,1763.44 h60
  text "116.00mil (2.946mm)" at 5993.16,1763.44 h60
  text "PTH" at 6629.72,1763.44 h60
  text "Round" at 6888.86,1763.44 h60
  text "Top Layer - Bottom Layer" at 7264.02,1763.44 h60
  text "2" at 5661.16,1639.12 h60
  text "47.24mil (1.200mm)" at 5993.16,1639.12 h60
  text "PTH" at 6629.72,1639.12 h60
  text "Slot" at 6888.86,1639.12 h60
  text "Top Layer - Bottom Layer" at 7264.02,1639.12 h60
  text "92 Total" at 5661.16,1514.8 h60
  text "Slot definitions :" at 5360.59,1427.78 h60
  text "Routed Path Length" at 5811.31,1427.78 h60
  text "= Calculated from tool start centre position to tool end centre position." at 6351.05,1427.78 h60
  text "Hole Length" at 5811.31,1378.05 h60
  text "= Routed Path Length + Tool Size = Slot length as defined in the PCB layout" at 6151.24,1378.05 h60
  text ".Layer_Name" at 577,-858.49 h60
M17 Embedded Cavity:
  text ".Layer_Name" at 577,-858.49 h60
M18 Embedded Assembly:
  text ".Layer_Name" at 577,-858.49 h60
M19 Embedded Keepout:
  text ".Layer_Name" at 577,-858.49 h60

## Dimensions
0,0 to 4798,0 on M2 Board Dimensions
0,0 to 0,2992 on M2 Board Dimensions
0,-400 to 1000,-400 on M2 Board Dimensions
